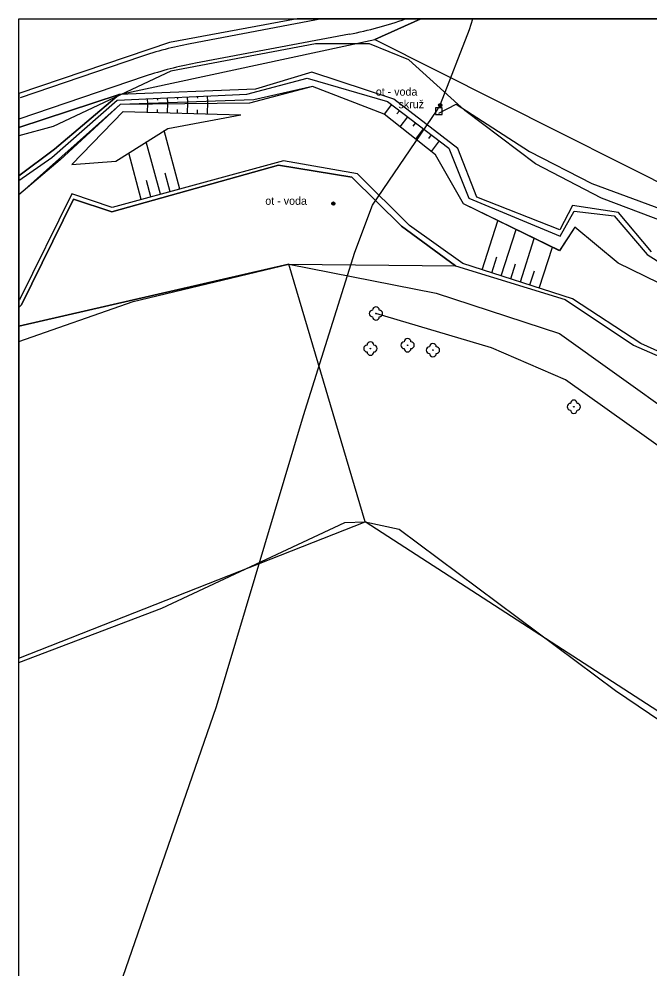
# Model space of a CAD drawing. Extents: x -574342 to -508101, y -1143544 to -1123894.
# Drawn here: x -508703.1 to -508608.5, y -1143258.4 to -1143116.1 of the extents above; entities that cross this region are included whole.
import ezdxf

# ---------------------------------------------------------------- set-up
doc = ezdxf.new("R2010")
doc.units = 0
for name, color, linetype in [('01_PARCELY_NAVRH_PC', 7, 'Continuous'), ('01_PARCELY_NAVRH_VHO', 7, 'Continuous'), ('01_PARCELY_NAVRH_ZPF', 7, 'Continuous'), ('01_PARCELY_NAVRH_ŽP', 7, 'Continuous'), ('05_VHO_V_TOK_STAV', 7, 'Continuous'), ('07_VODOVOD', 7, 'Continuous'), ('15', 7, 'Continuous'), ('37', 7, 'Continuous'), ('42', 7, 'Continuous'), ('52', 7, 'Continuous'), ('54', 7, 'Continuous'), ('55', 7, 'Continuous'), ('60', 7, 'Continuous'), ('61', 7, 'Continuous'), ('cesty', 7, 'Continuous'), ('Level 1', 7, 'Continuous'), ('PC_koruna', 7, 'Continuous')]:
    doc.layers.add(name, color=color, linetype=linetype)

msp = doc.modelspace()

# ---------------------------------------------------------------- linework, layer by layer
at = {"layer": '01_PARCELY_NAVRH_PC'}
for p, q in [((-508642.79, -1143116.06), (-508661.33, -1143116.06)), ((-508703.1, -1143127.21), (-508703.1, -1143132.33))]:
    msp.add_line(p, q, dxfattribs=at)
for points in [[(-508661.33, -1143116.06), (-508680.49, -1143119.57), (-508703.1, -1143127.21)], [(-508703.1, -1143132.33), (-508688.04, -1143127.38), (-508649.66, -1143119.13), (-508642.79, -1143116.06)]]:
    msp.add_lwpolyline(points, dxfattribs=at)
at = {"layer": '01_PARCELY_NAVRH_VHO'}
msp.add_line((-508703.1, -1143139.56), (-508703.1, -1143159.33), dxfattribs=at)
for points in [[(-508608.16, -1143150.99), (-508613.1, -1143145.09), (-508620.01, -1143144.01), (-508621.92, -1143147.67), (-508634.39, -1143142.78), (-508637.2, -1143135.49), (-508646.81, -1143128.1), (-508659.14, -1143124.02), (-508667.57, -1143126.58), (-508688.04, -1143127.38), (-508697.75, -1143135.59), (-508703.1, -1143139.56)], [(-508703.1, -1143159.33), (-508702.71, -1143158.91), (-508694.89, -1143143.1), (-508689.16, -1143144.96), (-508664.14, -1143138), (-508653.15, -1143139.78), (-508645.7, -1143147.14), (-508637.59, -1143153.08), (-508621.09, -1143158.13), (-508610.87, -1143164.96), (-508585.59, -1143176.01)]]:
    msp.add_lwpolyline(points, dxfattribs=at)
at = {"layer": '01_PARCELY_NAVRH_ZPF'}
msp.add_line((-508703.1, -1143162.14), (-508703.1, -1143211.95), dxfattribs=at)
msp.add_lwpolyline([(-508703.1, -1143211.95), (-508651.11, -1143191.46), (-508662.59, -1143152.85), (-508703.1, -1143162.14)], dxfattribs=at)
at = {"layer": '01_PARCELY_NAVRH_ŽP'}
for p, q in [((-508510.18, -1143116.06), (-508642.79, -1143116.06)), ((-508703.1, -1143132.33), (-508703.1, -1143139.56)), ((-508703.1, -1143159.33), (-508703.1, -1143162.14))]:
    msp.add_line(p, q, dxfattribs=at)
for points in [[(-508642.79, -1143116.06), (-508649.66, -1143119.13), (-508584.79, -1143151.71), (-508539.57, -1143146.61), (-508530.41, -1143150.9), (-508519.02, -1143135.54), (-508515.95, -1143130.65), (-508510.18, -1143116.06)], [(-508608.16, -1143150.99), (-508613.1, -1143145.09), (-508620.01, -1143144.01), (-508621.92, -1143147.67), (-508634.39, -1143142.78), (-508637.2, -1143135.49), (-508646.81, -1143128.1), (-508659.14, -1143124.02), (-508667.57, -1143126.58), (-508688.04, -1143127.38), (-508649.66, -1143119.13), (-508584.79, -1143151.71)], [(-508703.1, -1143139.56), (-508697.75, -1143135.59), (-508688.04, -1143127.38), (-508703.1, -1143132.33)], [(-508703.1, -1143162.14), (-508662.59, -1143152.85), (-508637.59, -1143153.08), (-508645.7, -1143147.14), (-508653.15, -1143139.78), (-508664.14, -1143138), (-508689.16, -1143144.96), (-508694.89, -1143143.1), (-508702.71, -1143158.91), (-508703.1, -1143159.33)]]:
    msp.add_lwpolyline(points, dxfattribs=at)
msp.add_lwpolyline([(-508555.03, -1143173.64), (-508548.66, -1143186.8), (-508549.63, -1143198.15), (-508549.79, -1143203.71), (-508547.53, -1143223.9), (-508542.99, -1143242.68), (-508538.24, -1143253.15), (-508539.95, -1143255.3), (-508547.25, -1143258.62), (-508651.11, -1143191.46), (-508662.59, -1143152.85), (-508637.59, -1143153.08), (-508621.09, -1143158.13), (-508610.87, -1143164.96), (-508585.59, -1143176.01), (-508569.25, -1143175.97)], close=True, dxfattribs=at)
at = {"layer": '05_VHO_V_TOK_STAV'}
msp.add_lwpolyline([(-508598.91, -1143159.61), (-508613.15, -1143152.7), (-508619.64, -1143147.26), (-508621.98, -1143150.8), (-508636.38, -1143143.79), (-508640.58, -1143136.45), (-508648.26, -1143130.35), (-508659.04, -1143126.17), (-508668.47, -1143128.69), (-508687.92, -1143128.89), (-508703.1, -1143142.43)], dxfattribs=at)
at = {"layer": '07_VODOVOD'}
for points in [[(-508703.1, -1143306.35), (-508693.81, -1143277.97), (-508673.43, -1143219.17), (-508660.38, -1143175.54), (-508652.67, -1143151.05), (-508650.03, -1143144), (-508640.33, -1143129.73), (-508639.81, -1143128.82), (-508635.48, -1143117.64), (-508634.95, -1143116.06)], [(-508640.05, -1143130.18), (-508637.48, -1143128.83), (-508626.48, -1143135.95), (-508617.09, -1143140.73), (-508602.61, -1143146.08), (-508586.87, -1143149.65), (-508578.03, -1143148.66), (-508571.02, -1143145.86), (-508562.51, -1143139.92), (-508546.01, -1143124.95), (-508535.68, -1143117.17), (-508534.43, -1143116.06)]]:
    msp.add_lwpolyline(points, dxfattribs=at)
at = {"layer": '37'}
msp.add_lwpolyline([(-508547.92, -1143166.82), (-508553.16, -1143167.82), (-508560.33, -1143168.91), (-508565.27, -1143165.89), (-508574.31, -1143168.46), (-508577.98, -1143162.03), (-508590.48, -1143165.72), (-508598.91, -1143159.61), (-508613.15, -1143152.7), (-508619.64, -1143147.26), (-508621.96, -1143150.81), (-508636.38, -1143143.79), (-508640.58, -1143136.45), (-508648.26, -1143130.35), (-508659.04, -1143126.17), (-508667.83, -1143128.19), (-508687.89, -1143128.88), (-508696.93, -1143137.18), (-508703.1, -1143142.43)], dxfattribs=at)
msp.add_lwpolyline([(-508547.92, -1143166.82), (-508553.16, -1143167.82), (-508560.33, -1143168.91), (-508565.27, -1143165.89), (-508574.31, -1143168.46), (-508577.98, -1143162.03), (-508590.48, -1143165.72), (-508598.91, -1143159.61), (-508613.15, -1143152.7), (-508619.64, -1143147.26), (-508621.96, -1143150.81), (-508636.38, -1143143.79), (-508640.58, -1143136.45), (-508648.26, -1143130.35), (-508659.04, -1143126.17), (-508667.83, -1143128.19), (-508687.89, -1143128.88), (-508696.93, -1143137.18), (-508703.1, -1143142.43)], dxfattribs=at)
at = {"layer": '42'}
for points in [[(-508537.36, -1143120.57), (-508572.46, -1143148.95), (-508584.79, -1143151.71), (-508598.2, -1143149.51), (-508615.67, -1143142.95), (-508625.58, -1143137.77), (-508636.15, -1143129.8), (-508644.59, -1143122.18), (-508650.46, -1143119.78), (-508658.6, -1143119.8), (-508680.31, -1143123.88), (-508697.98, -1143132.18), (-508703.1, -1143133.59)], [(-508537.36, -1143120.57), (-508572.46, -1143148.95), (-508584.79, -1143151.71), (-508598.2, -1143149.51), (-508615.67, -1143142.95), (-508625.58, -1143137.77), (-508636.15, -1143129.8), (-508644.59, -1143122.18), (-508650.46, -1143119.78), (-508658.6, -1143119.8), (-508680.31, -1143123.88), (-508697.98, -1143132.18), (-508703.1, -1143133.59)], [(-508703.1, -1143164.41), (-508685.93, -1143158.43), (-508662.59, -1143152.85), (-508640.45, -1143157.16), (-508621.97, -1143163.24), (-508595.81, -1143181.91), (-508584.52, -1143185.46)], [(-508703.1, -1143164.41), (-508685.93, -1143158.43), (-508662.59, -1143152.85), (-508640.45, -1143157.16), (-508621.97, -1143163.24), (-508595.81, -1143181.91), (-508584.52, -1143185.46)], [(-508703.1, -1143212.56), (-508681.67, -1143204.42), (-508654.2, -1143191.6)], [(-508703.1, -1143212.56), (-508681.67, -1143204.42), (-508654.2, -1143191.6)], [(-508654.2, -1143191.6), (-508651.11, -1143191.46), (-508646.05, -1143192.58), (-508613.56, -1143216.76), (-508566.08, -1143248.87), (-508547.92, -1143260.05), (-508536.29, -1143266.06), (-508529.87, -1143271.02), (-508526.62, -1143279.23), (-508525.63, -1143286.24)], [(-508654.2, -1143191.6), (-508651.11, -1143191.46), (-508646.05, -1143192.58), (-508613.56, -1143216.76), (-508566.08, -1143248.87), (-508547.92, -1143260.05), (-508536.29, -1143266.06), (-508529.87, -1143271.02), (-508526.62, -1143279.23), (-508525.63, -1143286.24)]]:
    msp.add_lwpolyline(points, dxfattribs=at)
at = {"layer": '52'}
msp.add_lwpolyline([(-508640.57, -1143130.36), (-508639.57, -1143130.36), (-508639.57, -1143129.36), (-508640.57, -1143129.36)], close=True, dxfattribs=at)
for centre, radius in [((-508639.85, -1143129), 0.25), ((-508639.85, -1143129), 0.158), ((-508639.85, -1143129), 0.05), ((-508655.91, -1143143.74), 0.25), ((-508655.91, -1143143.74), 0.158), ((-508655.91, -1143143.74), 0.05)]:
    msp.add_circle(centre, radius, dxfattribs=at)
at = {"layer": '54'}
for centre in [(-508649.51, -1143160.24), (-508644.76, -1143165), (-508650.35, -1143165.5), (-508640.96, -1143165.72), (-508619.82, -1143174.21)]:
    msp.add_circle(centre, 0.05, dxfattribs=at)
for centre, start, end in [((-508649.51, -1143159.74), 0, 180), ((-508650.01, -1143160.24), 90, 270), ((-508649.01, -1143160.24), 270, 90), ((-508649.51, -1143160.74), 180, 0), ((-508650.35, -1143165), 0, 180), ((-508645.26, -1143165), 90, 270), ((-508644.76, -1143164.5), 0, 180), ((-508644.26, -1143165), 270, 90), ((-508640.96, -1143165.22), 0, 180), ((-508650.85, -1143165.5), 90, 270), ((-508650.35, -1143166), 180, 0), ((-508649.85, -1143165.5), 270, 90), ((-508644.76, -1143165.5), 180, 0), ((-508641.46, -1143165.72), 90, 270), ((-508640.96, -1143166.22), 180, 0), ((-508640.46, -1143165.72), 270, 90), ((-508619.82, -1143173.71), 0, 180), ((-508620.32, -1143174.21), 90, 270), ((-508619.82, -1143174.71), 180, 0), ((-508619.32, -1143174.21), 270, 90)]:
    msp.add_arc(centre, 0.5, start, end, dxfattribs=at)
at = {"layer": '55'}
msp.add_lwpolyline([(-508589.09, -1143191.49), (-508596.07, -1143187.97), (-508621.05, -1143170.17), (-508632.19, -1143165.37), (-508649.51, -1143160.24)], dxfattribs=at)
msp.add_lwpolyline([(-508589.09, -1143191.49), (-508596.07, -1143187.97), (-508621.05, -1143170.17), (-508632.19, -1143165.37), (-508649.51, -1143160.24)], dxfattribs=at)
at = {"layer": '60'}
for points in [[(-508703.1, -1143140.29), (-508698.16, -1143136.85), (-508688.37, -1143128.25), (-508668.9, -1143127.33), (-508659.82, -1143124.93), (-508647.79, -1143128.43), (-508638.56, -1143135.42), (-508635.55, -1143142.94), (-508621.88, -1143148.61), (-508619.77, -1143144.86), (-508613.75, -1143145.58), (-508608.81, -1143151.36), (-508600.34, -1143156.71), (-508596.68, -1143154.49), (-508594.55, -1143156.75), (-508588.4, -1143163.81), (-508578.74, -1143160.36), (-508571.93, -1143166.89), (-508565.81, -1143164.6), (-508560.33, -1143167.09), (-508553.79, -1143165.29), (-508547.52, -1143164.27)], [(-508703.1, -1143140.29), (-508698.16, -1143136.85), (-508688.37, -1143128.25), (-508668.9, -1143127.33), (-508659.82, -1143124.93), (-508647.79, -1143128.43), (-508638.56, -1143135.42), (-508635.55, -1143142.94), (-508621.88, -1143148.61), (-508619.77, -1143144.86), (-508613.75, -1143145.58), (-508608.81, -1143151.36), (-508600.34, -1143156.71), (-508596.68, -1143154.49), (-508594.55, -1143156.75), (-508588.4, -1143163.81), (-508578.74, -1143160.36), (-508571.93, -1143166.89), (-508565.81, -1143164.6), (-508560.33, -1143167.09), (-508553.79, -1143165.29), (-508547.52, -1143164.27)], [(-508695.18, -1143137.87), (-508687.46, -1143129.92), (-508669.79, -1143130.45)], [(-508695.18, -1143137.87), (-508687.46, -1143129.92), (-508669.79, -1143130.45)], [(-508695.18, -1143137.87), (-508688.58, -1143137.38), (-508680.75, -1143132.46), (-508669.79, -1143130.45)], [(-508695.18, -1143137.87), (-508688.58, -1143137.38), (-508680.75, -1143132.46), (-508669.79, -1143130.45)], [(-508549.33, -1143169.24), (-508554.03, -1143169.86), (-508560.83, -1143169.76), (-508569.44, -1143175.37), (-508585.17, -1143175.34), (-508593.54, -1143172.04), (-508609.76, -1143164.75), (-508620.02, -1143158.01), (-508636.47, -1143152.72), (-508644.49, -1143147.03), (-508652.28, -1143139.28), (-508663.38, -1143137.35), (-508689.1, -1143144.32), (-508695.18, -1143142.29), (-508703.02, -1143158.17), (-508703.1, -1143158.26)], [(-508549.33, -1143169.24), (-508554.03, -1143169.86), (-508560.83, -1143169.76), (-508569.44, -1143175.37), (-508585.17, -1143175.34), (-508593.54, -1143172.04), (-508609.76, -1143164.75), (-508620.02, -1143158.01), (-508636.47, -1143152.72), (-508644.49, -1143147.03), (-508652.28, -1143139.28), (-508663.38, -1143137.35), (-508689.1, -1143144.32), (-508695.18, -1143142.29), (-508703.02, -1143158.17), (-508703.1, -1143158.26)]]:
    msp.add_lwpolyline(points, dxfattribs=at)
at = {"layer": '61'}
for p, q in [((-508680.83, -1143127.9), (-508680.8, -1143128.64)), ((-508680.83, -1143127.9), (-508680.8, -1143128.64)), ((-508679.33, -1143127.83), (-508679.32, -1143128.08)), ((-508679.33, -1143127.83), (-508679.32, -1143128.08)), ((-508677.83, -1143127.76), (-508677.8, -1143128.54)), ((-508677.83, -1143127.76), (-508677.8, -1143128.54)), ((-508676.34, -1143127.68), (-508676.32, -1143127.95)), ((-508676.34, -1143127.68), (-508676.32, -1143127.95)), ((-508674.84, -1143127.61), (-508674.8, -1143128.44)), ((-508674.84, -1143127.61), (-508674.8, -1143128.44)), ((-508683.83, -1143128.04), (-508683.79, -1143128.75)), ((-508683.83, -1143128.04), (-508683.79, -1143128.75)), ((-508683.79, -1143130.03), (-508683.75, -1143128.75)), ((-508683.79, -1143130.03), (-508683.75, -1143128.75)), ((-508682.33, -1143127.97), (-508682.32, -1143128.21)), ((-508682.33, -1143127.97), (-508682.32, -1143128.21)), ((-508680.79, -1143130.12), (-508680.75, -1143128.64)), ((-508680.79, -1143130.12), (-508680.75, -1143128.64)), ((-508677.8, -1143130.22), (-508677.74, -1143128.54)), ((-508677.8, -1143130.22), (-508677.74, -1143128.54)), ((-508674.8, -1143130.31), (-508674.74, -1143128.44)), ((-508674.8, -1143130.31), (-508674.74, -1143128.44)), ((-508647.19, -1143128.9), (-508648.28, -1143130.34)), ((-508647.19, -1143128.9), (-508648.28, -1143130.34)), ((-508682.29, -1143130.08), (-508682.28, -1143129.62)), ((-508682.29, -1143130.08), (-508682.28, -1143129.62)), ((-508679.3, -1143130.17), (-508679.28, -1143129.64)), ((-508679.3, -1143130.17), (-508679.28, -1143129.64)), ((-508676.3, -1143130.26), (-508676.28, -1143129.67)), ((-508676.3, -1143130.26), (-508676.28, -1143129.67)), ((-508646, -1143129.81), (-508646.37, -1143130.3)), ((-508646, -1143129.81), (-508646.37, -1143130.3)), ((-508644.8, -1143130.71), (-508645.93, -1143132.21)), ((-508644.8, -1143130.71), (-508645.93, -1143132.21)), ((-508643.6, -1143131.62), (-508643.99, -1143132.13)), ((-508643.6, -1143131.62), (-508643.99, -1143132.13)), ((-508678.95, -1143141.56), (-508681.32, -1143132.8)), ((-508678.95, -1143141.56), (-508681.32, -1143132.8)), ((-508642.41, -1143132.52), (-508643.58, -1143134.08)), ((-508642.41, -1143132.52), (-508643.58, -1143134.08)), ((-508641.21, -1143133.43), (-508641.61, -1143133.96)), ((-508641.21, -1143133.43), (-508641.61, -1143133.96)), ((-508681.85, -1143142.35), (-508683.98, -1143134.47)), ((-508681.85, -1143142.35), (-508683.98, -1143134.47)), ((-508640.02, -1143134.33), (-508641.23, -1143135.94)), ((-508640.02, -1143134.33), (-508641.23, -1143135.94)), ((-508684.74, -1143143.13), (-508686.63, -1143136.14)), ((-508684.74, -1143143.13), (-508686.63, -1143136.14)), ((-508680.4, -1143141.96), (-508681.15, -1143139.18)), ((-508680.4, -1143141.96), (-508681.15, -1143139.18)), ((-508683.29, -1143142.74), (-508683.96, -1143140.26)), ((-508683.29, -1143142.74), (-508683.96, -1143140.26)), ((-508633.56, -1143153.66), (-508631.2, -1143146.32)), ((-508633.56, -1143153.66), (-508631.2, -1143146.32)), ((-508630.7, -1143154.58), (-508628.48, -1143147.64)), ((-508630.7, -1143154.58), (-508628.48, -1143147.64)), ((-508627.84, -1143155.5), (-508625.75, -1143148.97)), ((-508627.84, -1143155.5), (-508625.75, -1143148.97)), ((-508624.99, -1143156.41), (-508623.02, -1143150.29)), ((-508624.99, -1143156.41), (-508623.02, -1143150.29)), ((-508632.13, -1143154.12), (-508631.37, -1143151.74)), ((-508632.13, -1143154.12), (-508631.37, -1143151.74)), ((-508629.27, -1143155.04), (-508628.55, -1143152.8)), ((-508629.27, -1143155.04), (-508628.55, -1143152.8)), ((-508626.42, -1143155.95), (-508625.74, -1143153.85)), ((-508626.42, -1143155.95), (-508625.74, -1143153.85))]:
    msp.add_line(p, q, dxfattribs=at)
at = {"layer": 'cesty'}
for p, q in [((-508657.64, -1143116.06), (-508677.41, -1143119.77)), ((-508653.49, -1143118.33), (-508676.58, -1143122.67)), ((-508684.85, -1143121.72), (-508702.94, -1143127.86)), ((-508684.15, -1143124.65), (-508703.1, -1143131.08))]:
    msp.add_line(p, q, dxfattribs=at)
msp.add_arc((-508663.93, -1143062.8), 56.5, 280.6436, 289.516, dxfattribs=at)
at = {"layer": 'Level 1'}
msp.add_lwpolyline([(-508703.1, -1143116.06), (-508109.1, -1143116.06), (-508109.1, -1143536.06), (-508703.1, -1143536.06)], close=True, dxfattribs=at)
at = {"layer": 'PC_koruna'}
for centre, radius in [((-508667.35, -1143173.34), 54.5), ((-508666.33, -1143177.22), 55.5)]:
    msp.add_arc(centre, radius, 100.6436, 108.73, dxfattribs=at)

# ---------------------------------------------------------------- texts
at = {"layer": '15'}
for s, p in [('ot - voda', (-508649.54, -1143127.56)), ('ot - voda', (-508649.54, -1143127.56)), ('skruž', (-508646.13, -1143129.44)), ('skruž', (-508646.13, -1143129.44)), ('ot - voda', (-508666.12, -1143143.93)), ('ot - voda', (-508666.12, -1143143.93))]:
    msp.add_text(s, height=1.2, dxfattribs=at).set_placement(p)

doc.saveas('drawing.dxf')
